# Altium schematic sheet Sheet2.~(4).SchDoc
size A3
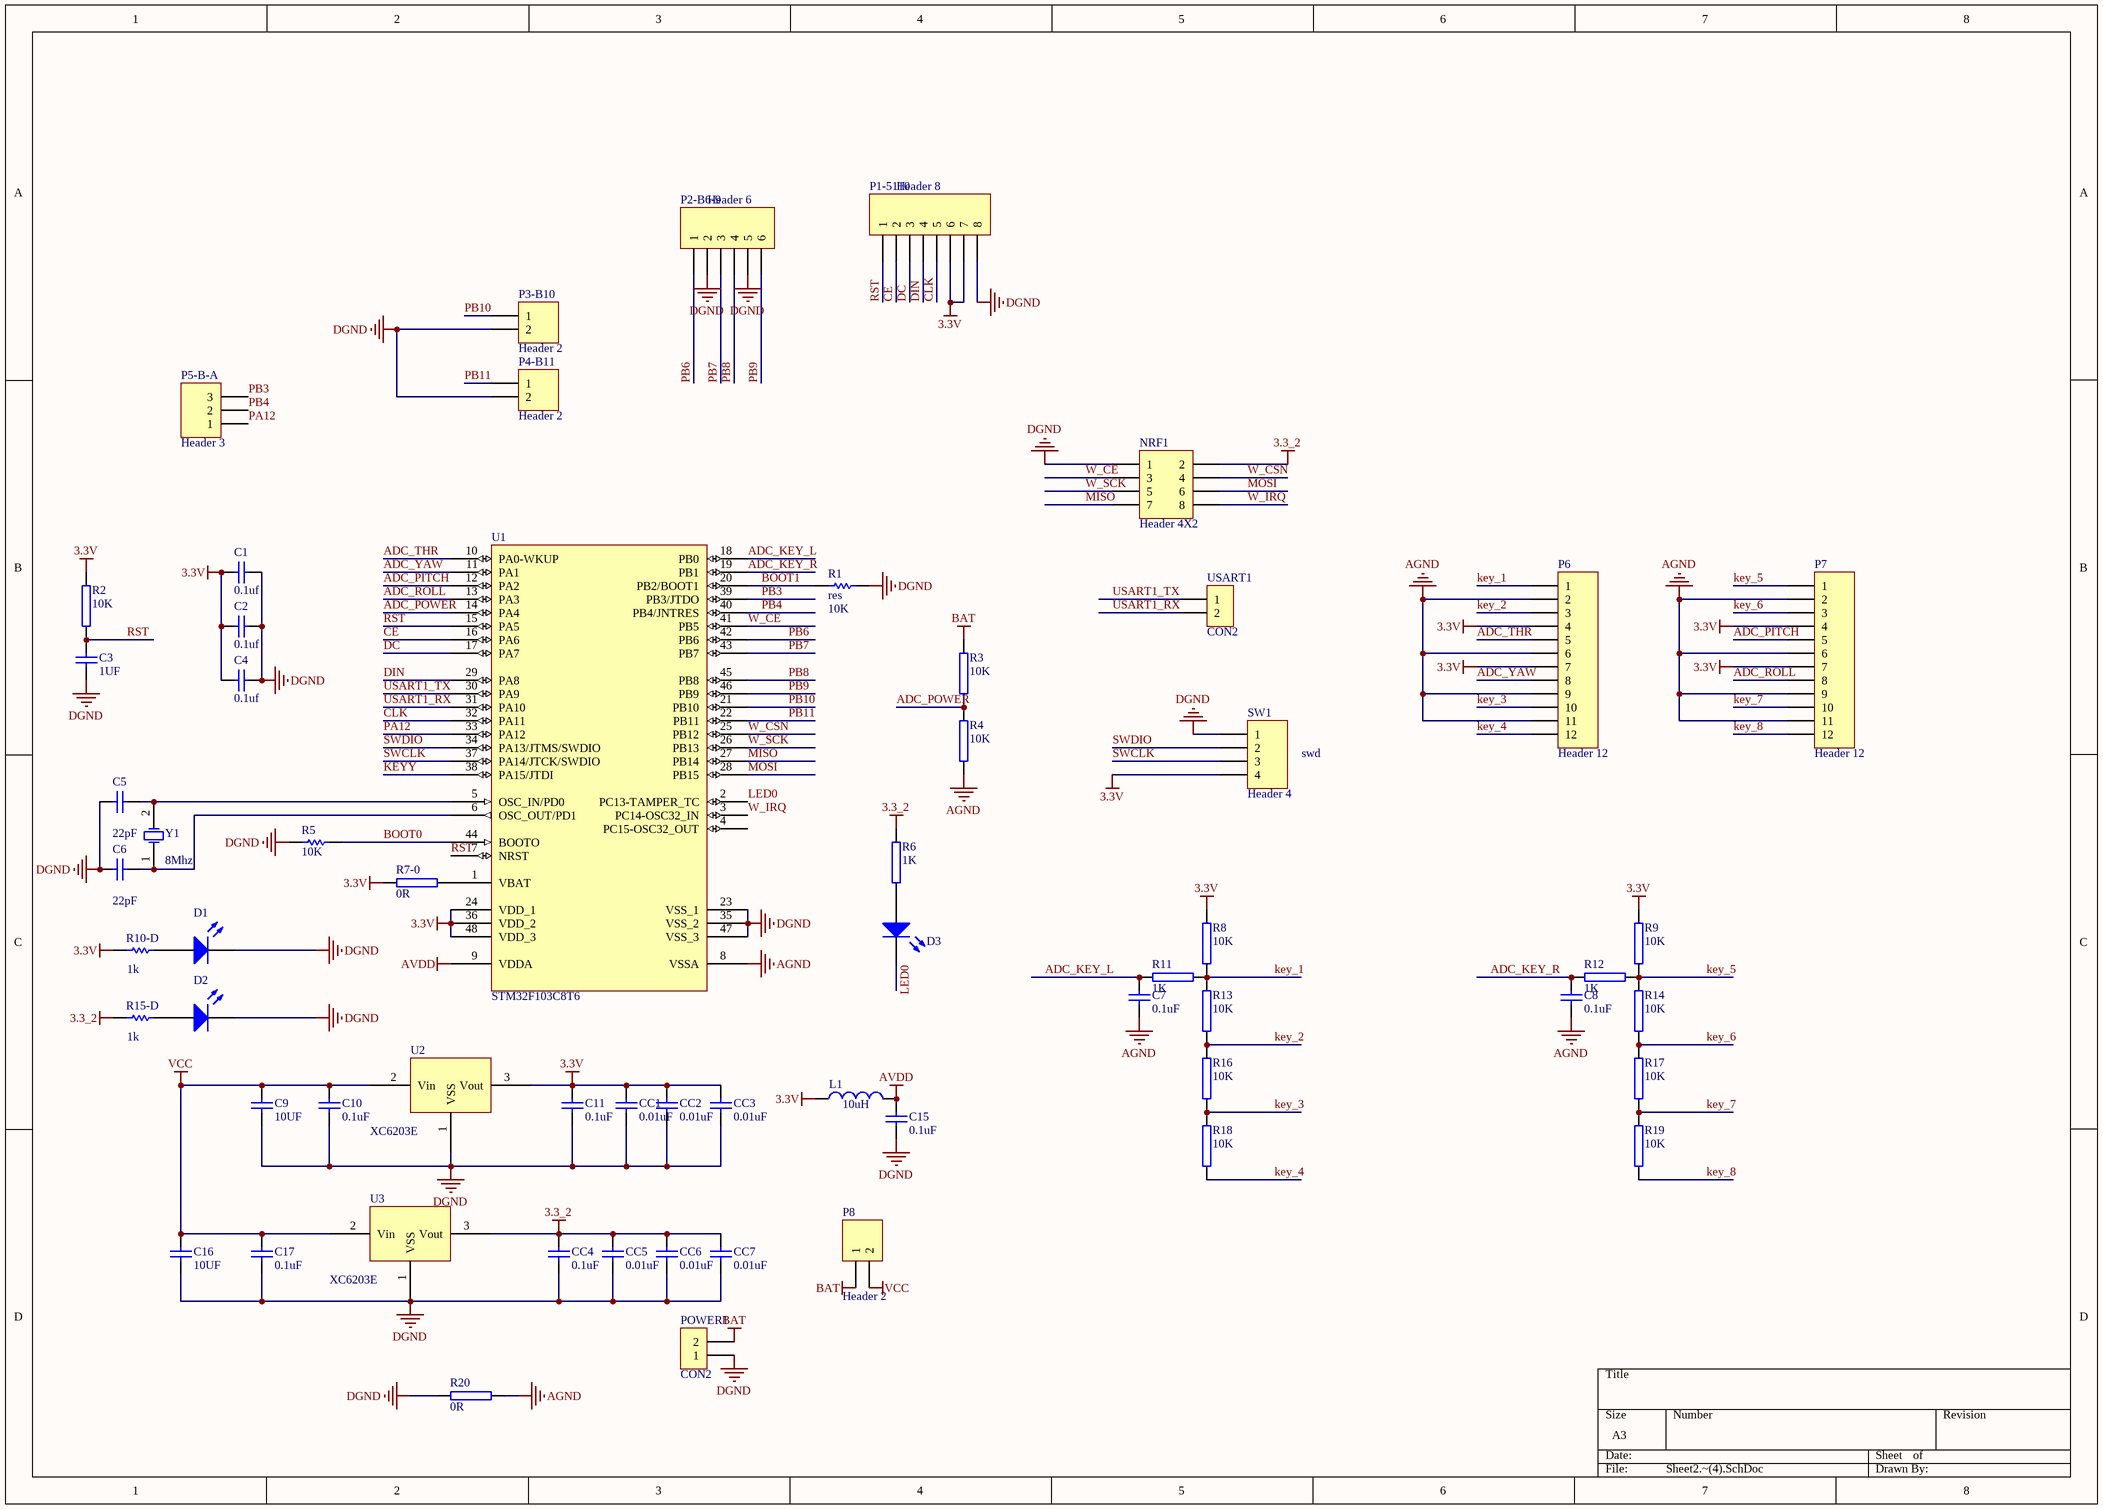
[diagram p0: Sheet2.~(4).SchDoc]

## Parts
C1  value 0.1uf  [0603c]  (hidden comment: cap)
C2  value 0.1uf  [0603c]  (hidden comment: cap)
C3  value 1UF  [0603c]  (hidden comment: cap)
C4  value 0.1uf  [0603c]  (hidden comment: cap)
C5  value 22pF  [0603c]  (hidden comment: cap)
C6  value 22pF  [0603c]  (hidden comment: cap)
C7  value 0.1uF  [0603c]  (hidden comment: cap)
C8  value 0.1uF  [0603c]  (hidden comment: cap)
C9  value 10UF  [0805]  (hidden comment: cap)
C10  value 0.1uF  [0603c]  (hidden comment: cap)
C11  value 0.1uF  [0603c]  (hidden comment: cap)
C15  value 0.1uF  [0603c]  (hidden comment: cap)
C16  value 10UF  [0805]  (hidden comment: cap)
C17  value 0.1uF  [0603c]  (hidden comment: cap)
CC1  value 0.01uF  [0603c]  (hidden comment: cap)
CC2  value 0.01uF  [0603c]  (hidden comment: cap)
CC3  value 0.01uF  [0603c]  (hidden comment: cap)
CC4  value 0.1uF  [0603c]  (hidden comment: cap)
CC5  value 0.01uF  [0603c]  (hidden comment: cap)
CC6  value 0.01uF  [0603c]  (hidden comment: cap)
CC7  value 0.01uF  [0603c]  (hidden comment: cap)
D1  LED0  [0805]  (value not drawn)
D2  LED0  [0805]  (value not drawn)
D3  LED0  [0805]  (value not drawn)
L1  value 10uH  [0805]  (hidden comment: Inductor)
NRF1  Header 4X2  [HDR2X4]
P1-5110  Header 8  [HDR1X8]
P2-B6-9  Header 6  [HDR1X6]
P3-B10  Header 2  [HDR1X2]
P4-B11  Header 2  [HDR1X2]
P5-B-A  Header 3  [HDR1X3]
P6  Header 12  [HDR1X12]
P7  Header 12  [HDR1X12]
P8  Header 2  [HDR1X2]
POWER1  CON2  [SIP2]
R1  res  res: 10K  [0603c]
R2  10K  [0603c]
R3  10K  [0603c]
R4  10K  [0603c]
R5  res: 10K  [0603c]  (hidden comment: res)
R6  1K  [0603c]
R7-0  0R  [0805]
R8  10K  [0603c]
R9  10K  [0603c]
R10-D  res: 1k  [0603c]  (hidden comment: res)
R11  1K  [0603c]
R12  1K  [0603c]
R13  10K  [0603c]
R14  10K  [0603c]
R15-D  res: 1k  [0603c]  (hidden comment: res)
R16  10K  [0603c]
R17  10K  [0603c]
R18  10K  [0603c]
R19  10K  [0603c]
R20  0R  [0805]
SW1  Header 4  [HDR1X4]
U1  STM32F103C8T6  [LQFP48S]
U2  XC6203E  [SOT-89]
U3  XC6203E  [SOT-89]
USART1  CON2  [SIP2]
Y1  5032xtal  [XTAL]  (value not drawn)

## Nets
3.3_2: CC4.2 CC5.2 CC6.2 CC7.2 NRF1.2 R6.2 R15-D.1 U3.3(Vout)
3.3V: C1.2 C2.2 C4.2 C11.2 CC1.2 CC2.2 CC3.2 L1.1 P1-5110.6 P1-5110.7 P6.4 P6.7 P7.4 P7.7 R2.2 R7-0.2 R8.2 R9.2 R10-D.1 SW1.4 U1.24(VDD_1) U1.36(VDD_2) U1.48(VDD_3) U2.3(Vout)
AGND: C7.1 C8.1 P6.2 P6.6 P6.9 P6.11 P7.2 P7.6 P7.9 P7.11 R4.1 R20.2 U1.8(VSSA)
AVDD: C15.2 L1.2 U1.9(VDDA)
BAT: P8.1 POWER1.2 R3.2
DGND: C1.1 C2.1 C3.1 C4.1 C5.1 C6.1 C9.1 C10.1 C11.1 C15.1 C16.1 C17.1 CC1.1 CC2.1 CC3.1 CC4.1 CC5.1 CC6.1 CC7.1 D1.2(K) D2.2(K) NRF1.1 P1-5110.8 P2-B6-9.2 P2-B6-9.5 P3-B10.2 P4-B11.2 POWER1.1 R1.2 R5.1 R20.1 SW1.1 U1.23(VSS_1) U1.35(VSS_2) U1.47(VSS_3) U2.1(VSS) U3.1(VSS)
VCC: C9.2 C10.2 C16.2 C17.2 P8.2 U2.2(Vin) U3.2(Vin)
ADC_KEY_L: C7.2 R11.2 U1.18(PB0)
ADC_KEY_R: C8.2 R12.2 U1.19(PB1)
ADC_PITCH: P7.5 U1.12(PA2)
ADC_POWER: R3.1 R4.2 U1.14(PA4)
ADC_ROLL: P7.8 U1.13(PA3)
ADC_THR: P6.5 U1.10(PA0-WKUP)
ADC_YAW: P6.8 U1.11(PA1)
BOOT0: R5.2 U1.44(BOOTO)
BOOT1: R1.1 U1.20(PB2/BOOT1)
CE: P1-5110.2 U1.16(PA6)
CLK: P1-5110.5 U1.32(PA11)
DC: P1-5110.3 U1.17(PA7)
DIN: P1-5110.4 U1.29(PA8)
key_1: P6.1 R8.1 R11.1 R13.2
key_2: P6.3 R13.1 R16.2
key_3: P6.10 R16.1 R18.2
key_4: P6.12 R18.1
key_5: P7.1 R9.1 R12.1 R14.2
key_6: P7.3 R14.1 R17.2
key_7: P7.10 R17.1 R19.2
key_8: P7.12 R19.1
KEYY: U1.38(PA15/JTDI)
LED0: D3.2(K) U1.2(PC13-TAMPER_TC)
MISO: NRF1.7 U1.27(PB14)
MOSI: NRF1.6 U1.28(PB15)
PA12: P5-B-A.1 U1.33(PA12)
PB3: P5-B-A.3 U1.39(PB3/JTDO)
PB4: P5-B-A.2 U1.40(PB4/JNTRES)
PB6: P2-B6-9.1 U1.42(PB6)
PB7: P2-B6-9.3 U1.43(PB7)
PB8: P2-B6-9.4 U1.45(PB8)
PB9: P2-B6-9.6 U1.46(PB9)
PB10: P3-B10.1 U1.21(PB10)
PB11: P4-B11.1 U1.22(PB11)
RST: C3.2 P1-5110.1 R2.1 U1.7(NRST) U1.15(PA5)
SWCLK: SW1.3 U1.37(PA14/JTCK/SWDIO)
SWDIO: SW1.2 U1.34(PA13/JTMS/SWDIO)
USART1_RX: U1.31(PA10) USART1.2
USART1_TX: U1.30(PA9) USART1.1
W_CE: NRF1.3 U1.41(PB5)
W_CSN: NRF1.4 U1.25(PB12)
W_IRQ: NRF1.8 U1.3(PC14-OSC32_IN)
W_SCK: NRF1.5 U1.26(PB13)
NetC5_2: C5.2 U1.5(OSC_IN/PD0) Y1.2(OSC2)
NetC6_2: C6.2 U1.6(OSC_OUT/PD1) Y1.1(OSC1)
NetD1_1: D1.1(A) R10-D.2
NetD2_1: D2.1(A) R15-D.2
NetD3_1: D3.1(A) R6.1
NetR7-0_1: R7-0.1 U1.1(VBAT)

Not connected (* = marked no-connect by the designer): U1 4(PC15-OSC32_OUT)

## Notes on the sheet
- swd

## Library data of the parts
D1-D3 = LED0: Typical INFRARED GaAs LED
NRF1 = Header 4X2: Header, 4-Pin, Dual row
P1-5110 = Header 8: Header, 8-Pin
P2-B6-9 = Header 6: Header, 6-Pin
P3-B10 P4-B11 P8 = Header 2: Header, 2-Pin
P5-B-A = Header 3: Header, 3-Pin
P6 P7 = Header 12: Header, 12-Pin
R2-R4 R6 R7-0 R8 R9 R11-R14 R16-R20 = RES
SW1 = Header 4: Header, 4-Pin
U2 U3 = XC6203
